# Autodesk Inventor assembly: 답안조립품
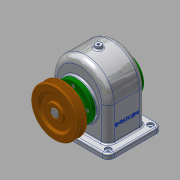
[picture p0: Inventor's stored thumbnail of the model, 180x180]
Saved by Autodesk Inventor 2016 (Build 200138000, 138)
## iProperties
Created: 2018-08
Part Number: 답안조립품
Document SubType Name: Assembly
Designer: 301-08
Author: 301-08
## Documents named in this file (14)
- C:\Users\301-08\Desktop\480811V1014\답안조립품.iam
- C:\Users\301-08\Desktop\480811V1014\본체.ipt
- C:\Users\301-08\Desktop\480811V1014\베어링 6203.ipt
- C:\Users\301-08\Desktop\480811V1014\축.ipt
- C:\Users\301-08\Desktop\480811V1014\키 6x6x22.ipt
- C:\Users\301-08\Desktop\480811V1014\부시.ipt
- C:\Users\301-08\Desktop\480811V1014\앞커버.ipt
- C:\Users\301-08\Desktop\480811V1014\뒤커버.ipt
- C:\Users\301-08\Desktop\480811V1014\볼트 M4.ipt
- C:\Users\301-08\Desktop\480811V1014\오일 실 28 40 8.ipt
- C:\Users\301-08\Desktop\480811V1014\키 5x5x18.ipt
- C:\Users\301-08\Desktop\480811V1014\V-벨트풀리.ipt
- C:\Users\301-08\Desktop\480811V1014\멈춤나사 M4.ipt
- C:\Users\301-08\Desktop\480811V1014\스퍼기어.ipt
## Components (1 placed, 1 different names)
1. V-벨트풀리:1
